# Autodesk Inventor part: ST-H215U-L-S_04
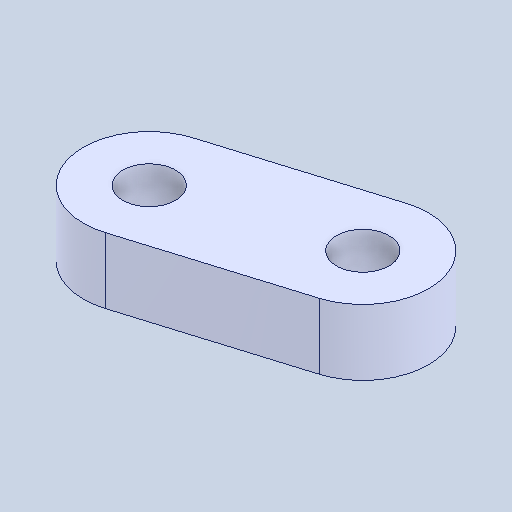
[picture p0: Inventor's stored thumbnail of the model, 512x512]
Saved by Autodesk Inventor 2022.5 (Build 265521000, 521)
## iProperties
Created: 2024-07
Part Number: ST-H215U-L-S_04
Material: 一般
Document SubType Name: Modeling
Designer: ImaoCorp
Density: 1 g/cm^3
Appearance: 既定
Author: ImaoCorp
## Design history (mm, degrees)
feature "ST-H215U-L-S_04"
node "ソリッド1"
